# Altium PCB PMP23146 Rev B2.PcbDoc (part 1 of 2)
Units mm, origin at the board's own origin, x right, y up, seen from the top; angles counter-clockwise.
Board outline 35 x 30 mm, 4 copper layers (Top Layer, Int1 (GND), Int2 (PWR), Bottom Layer), stack 0.912 mm thick; 83 components, 52 nets, 312 pads, 74 vias.
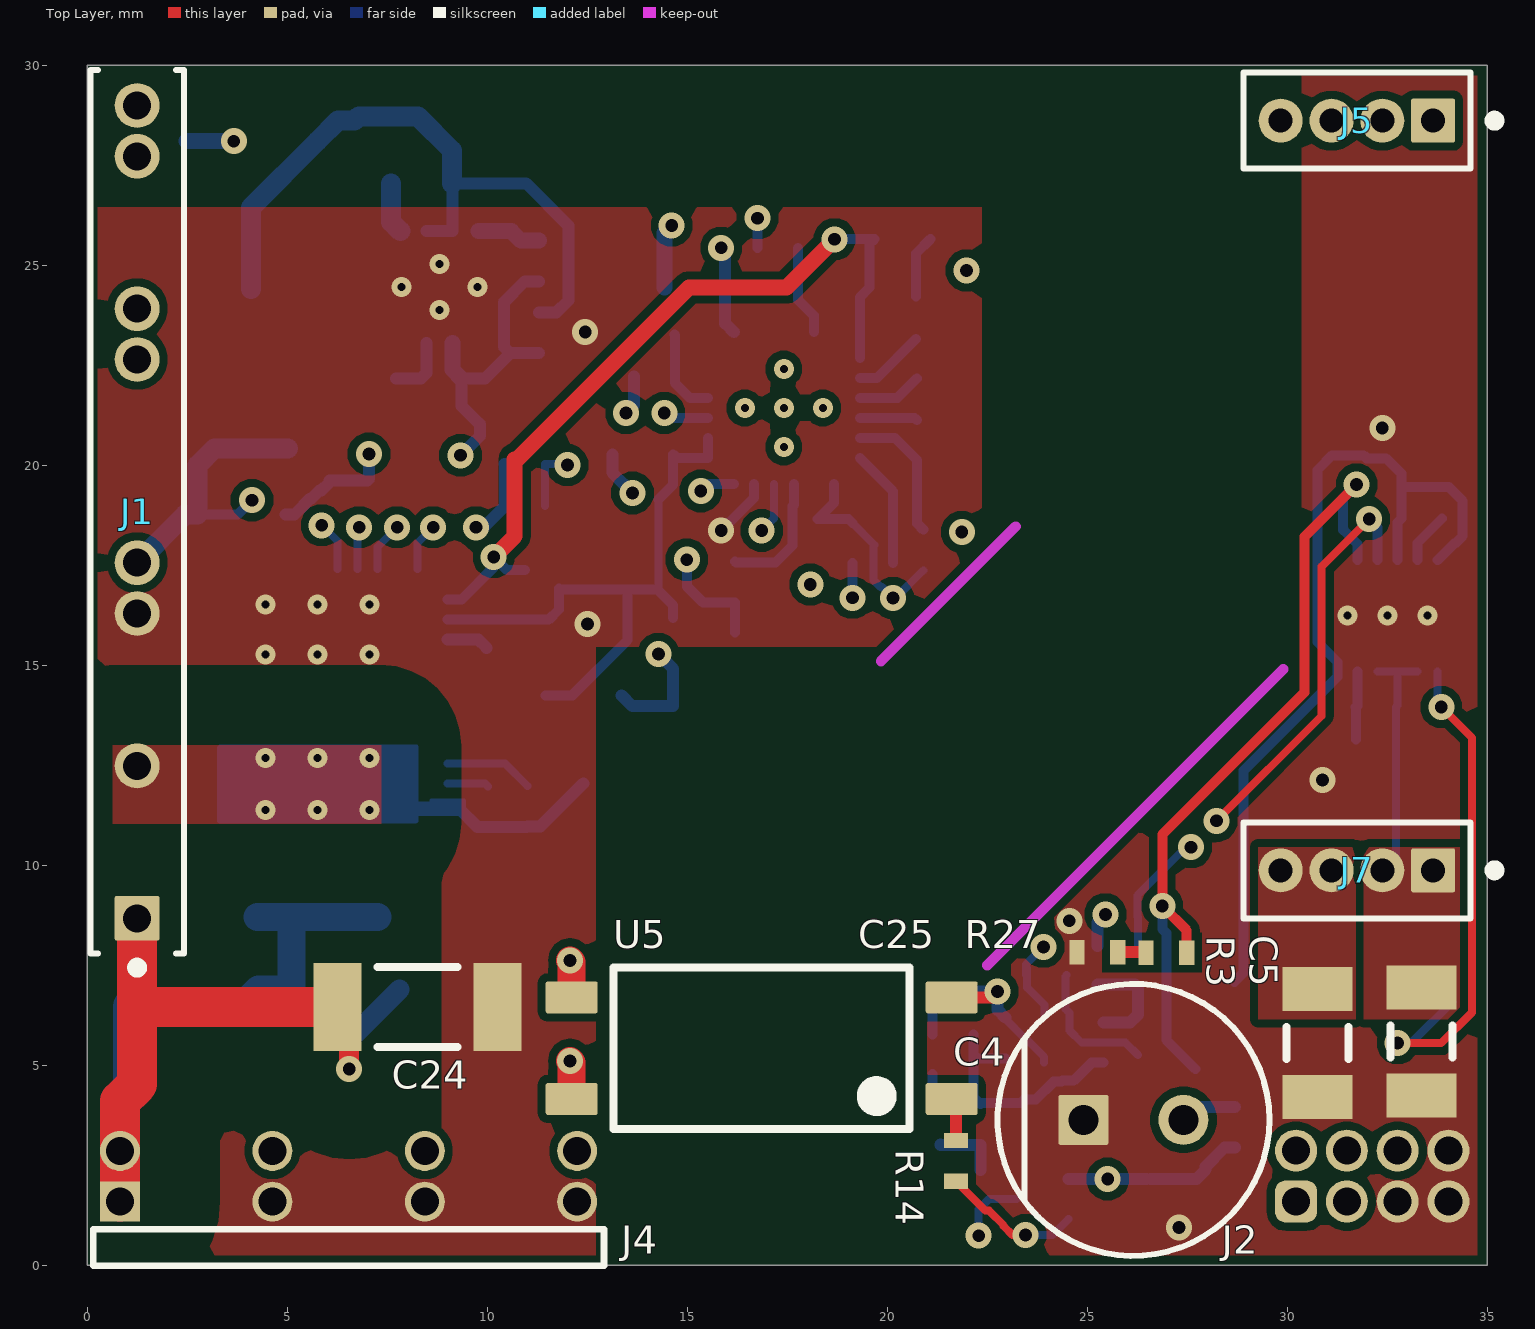
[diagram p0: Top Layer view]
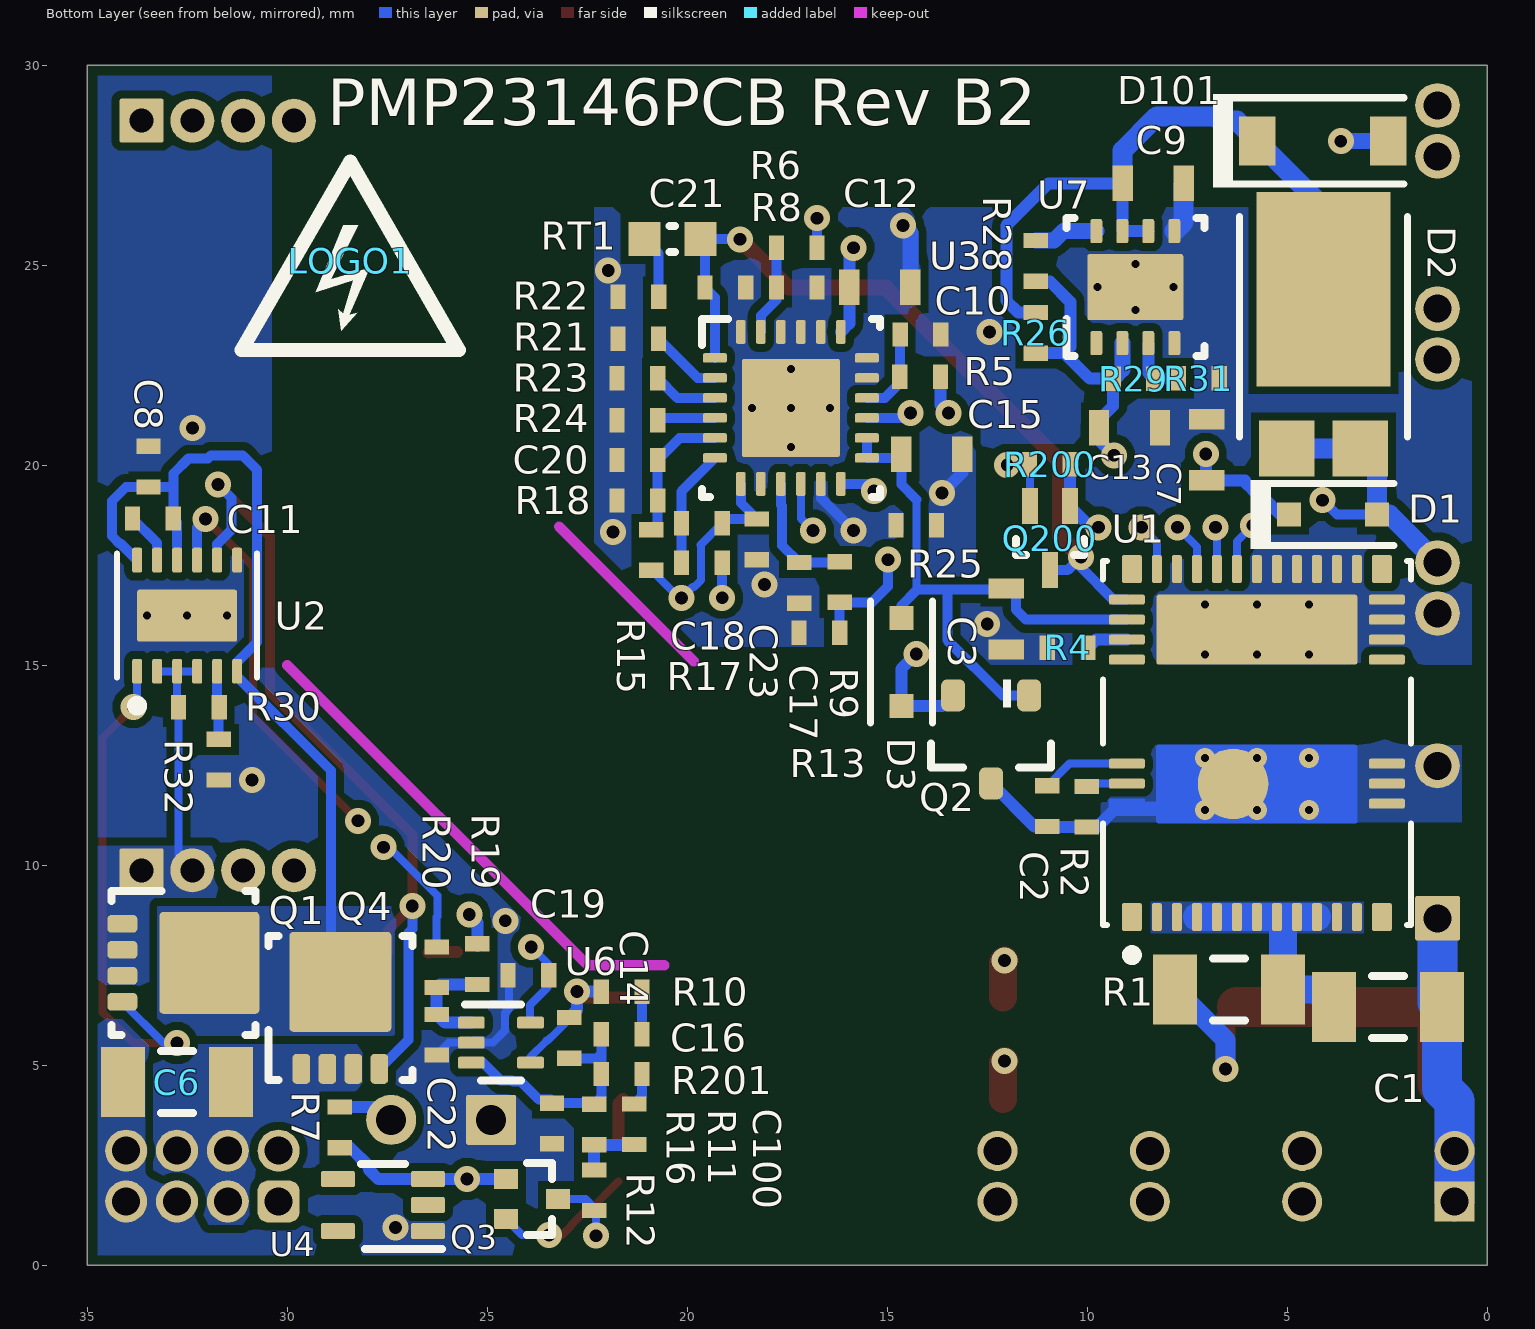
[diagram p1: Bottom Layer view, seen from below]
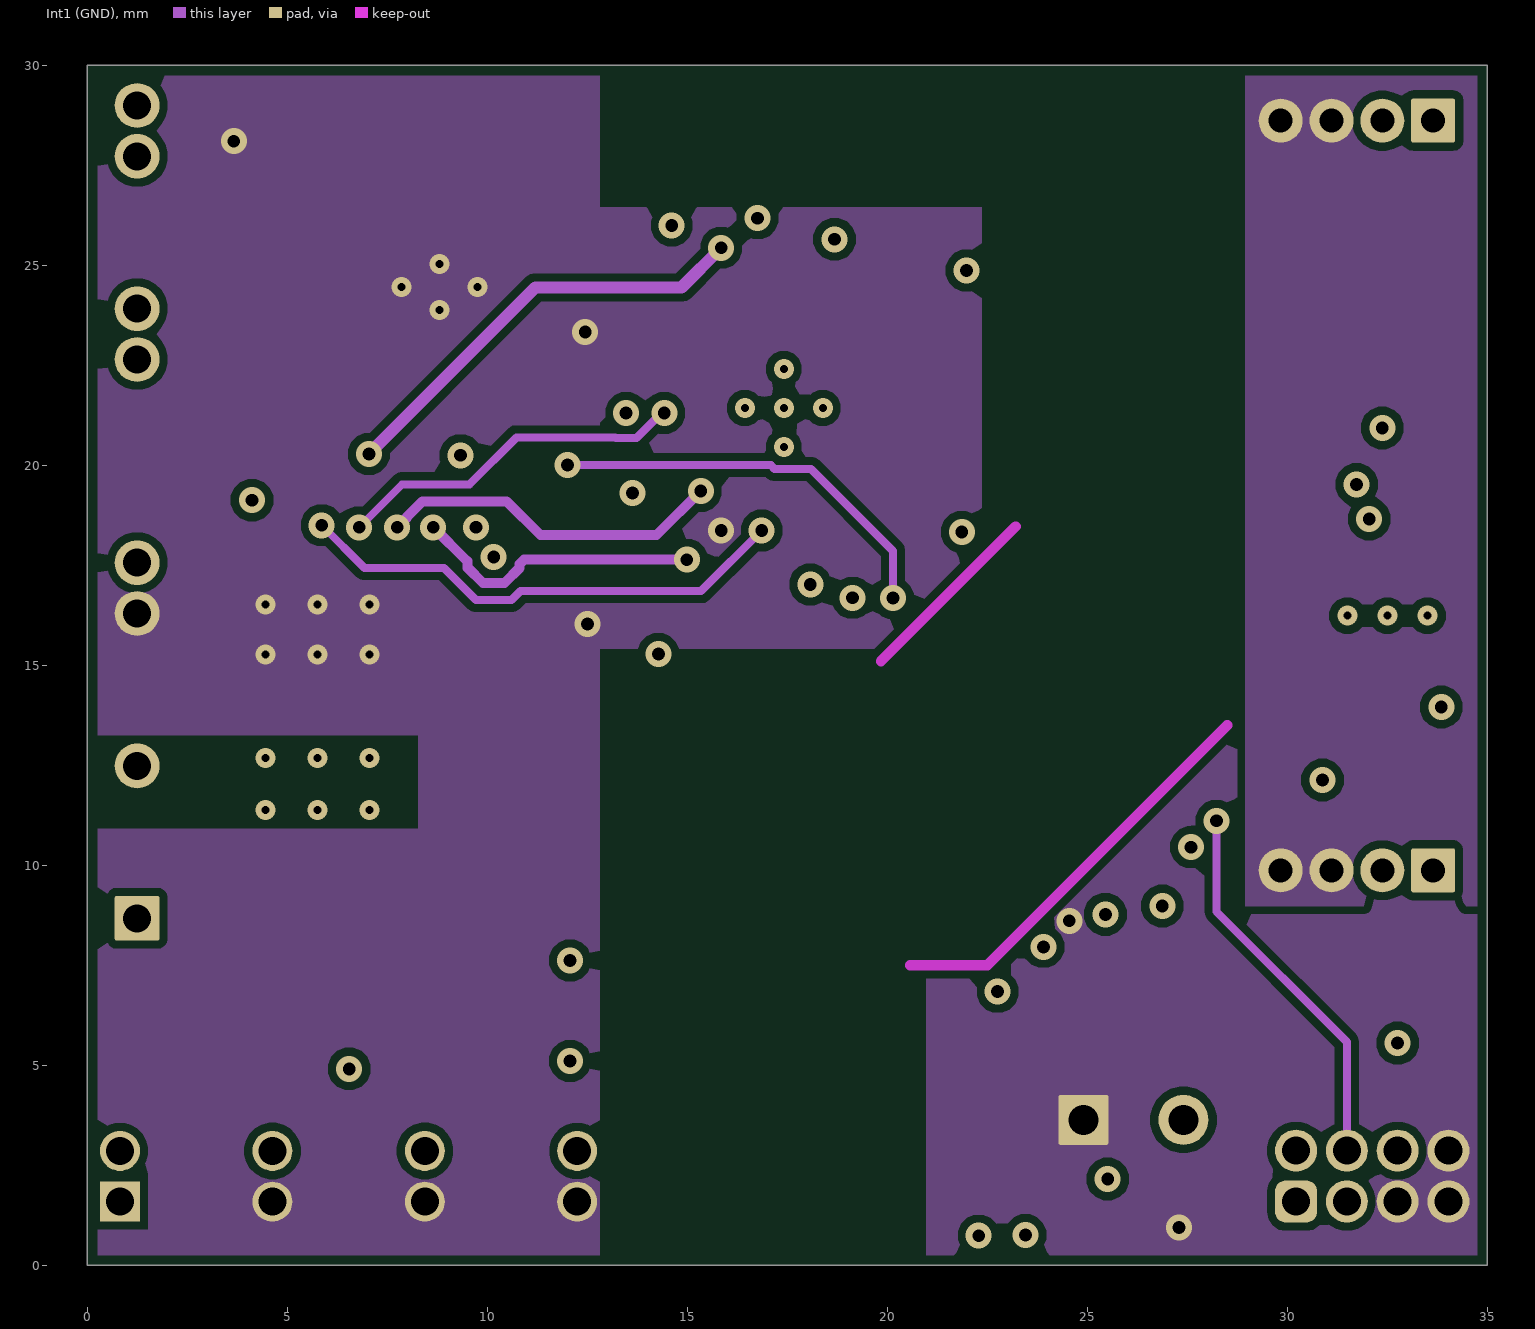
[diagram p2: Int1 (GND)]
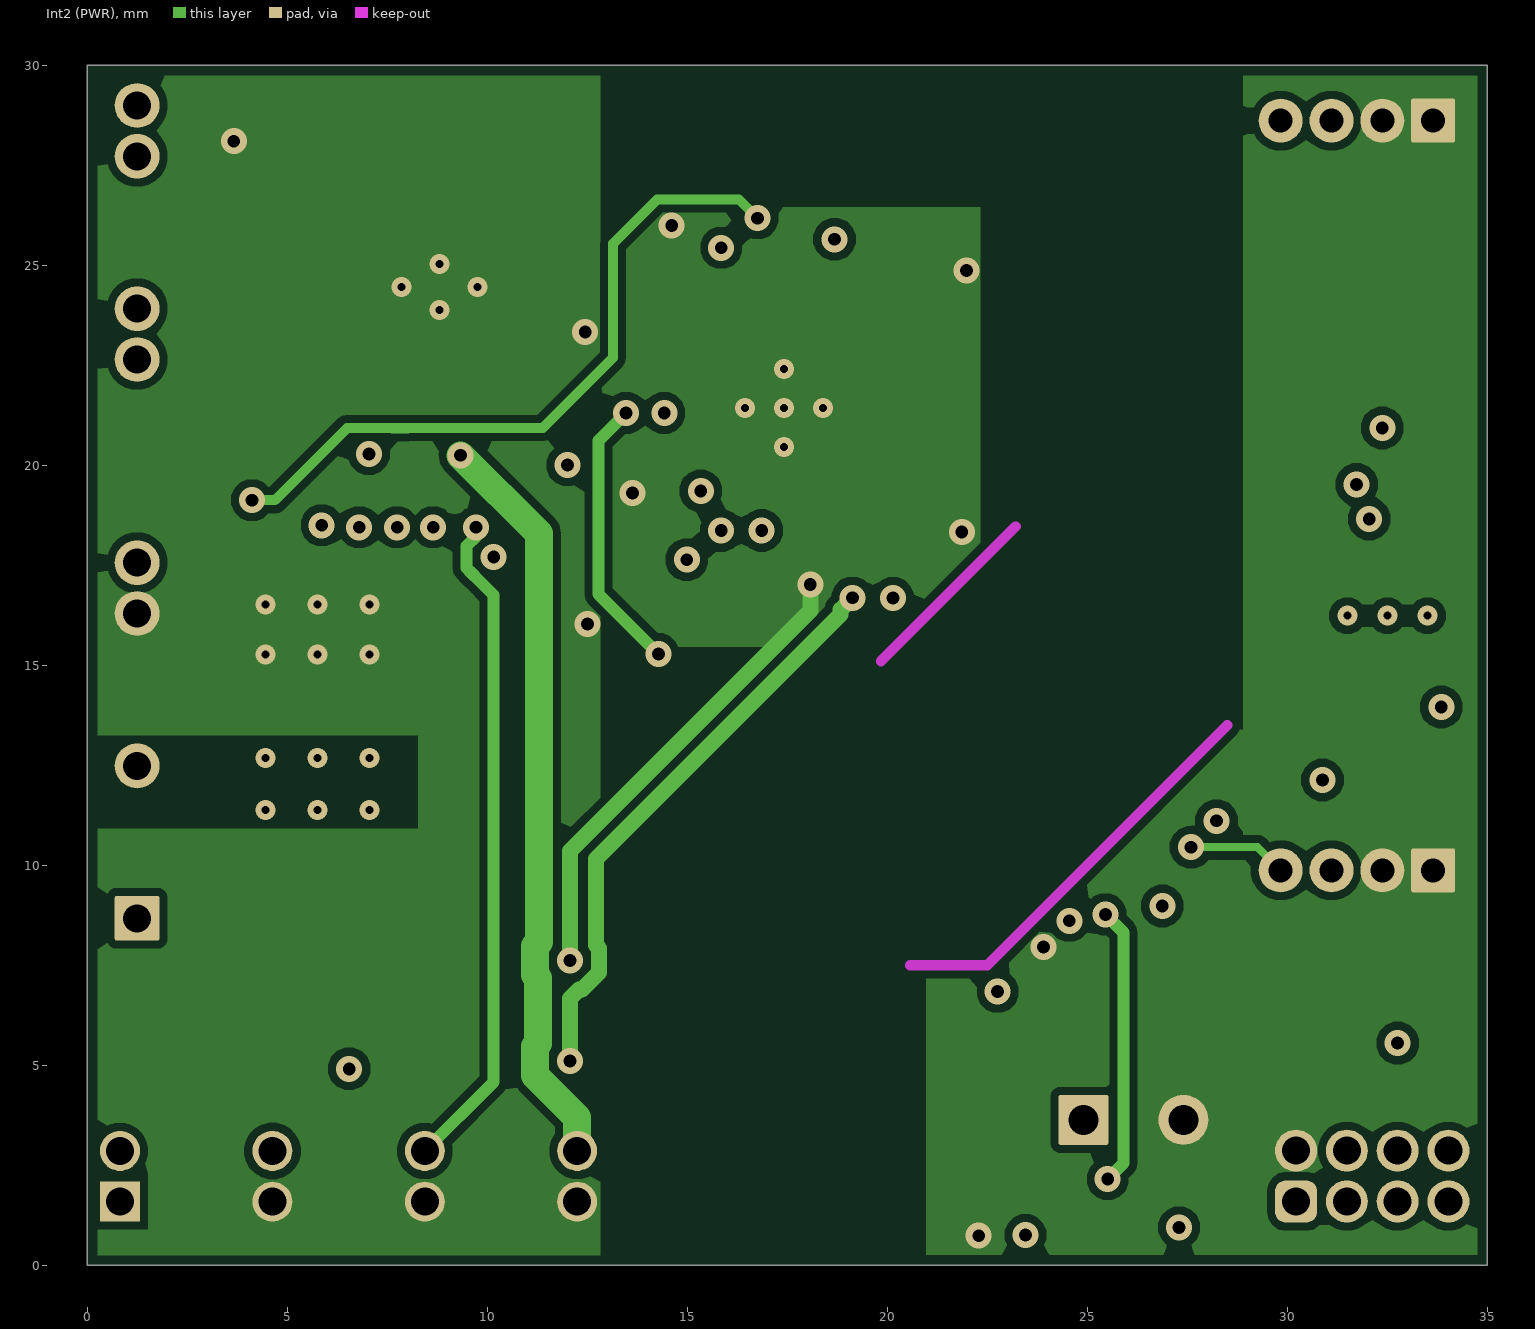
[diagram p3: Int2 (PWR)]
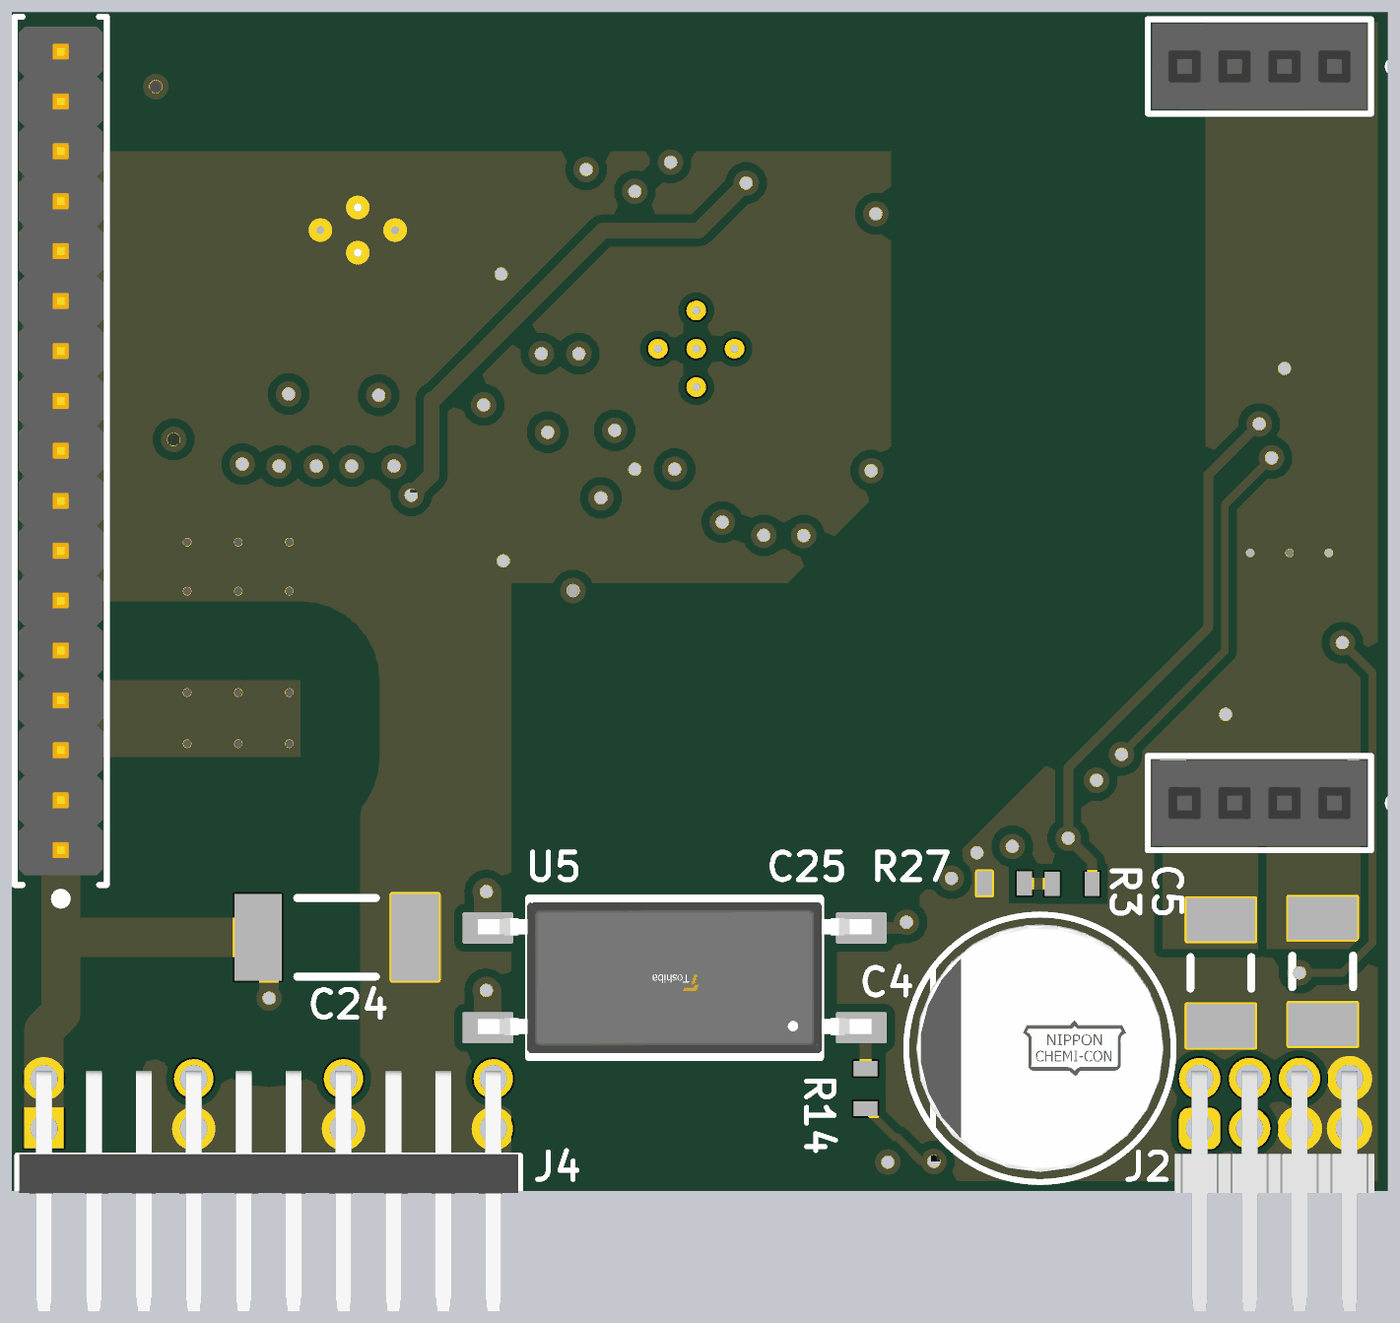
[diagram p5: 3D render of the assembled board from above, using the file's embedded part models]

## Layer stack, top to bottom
Top Solder: solder mask 0.0254, SM-001, Dk 4
Top Layer: signal copper 0.035
Dielectric 1: prepreg 0.1295, PP-017, Dk 4.3
Dielectric 2: prepreg 0.1295, PP-017, Dk 4.3
Int1 (GND): signal copper 0.035
Dielectric 3: core 0.254, Core-028, Dk 4.3
Int2 (PWR): signal copper 0.035
Dielectric 4: prepreg 0.1295, PP-017, Dk 4.3
Dielectric 5: prepreg 0.1295, PP-017, Dk 4.3
Bottom Layer: signal copper 0.035
Bottom Solder: solder mask 0.0254, SM-001, Dk 4

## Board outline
0,0 35,0 35,30 0,30

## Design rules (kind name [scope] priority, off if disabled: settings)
AcuteAngle [All] p1: minimum=5.00000000000000E+0000 checktracksonly=FALSE
AssemblyTestPointUsage [All] p1: valid=2
BoardOutlineClearance BoardOutlineClearance_Pri [InNet('P')] p1: gap=0.4 ignorepadtopadclearanceinfootprint=FALSE
BoardOutlineClearance BoardOutlineClearance_MountingHoles [OnCopper and InComponentClass('Mounting Holes')] p2: gap=0.635 ignorepadtopadclearanceinfootprint=FALSE
BoardOutlineClearance BoardOutlineClearance_Poly [OnCopper and InPoly] p3: gap=0.25 ignorepadtopadclearanceinfootprint=FALSE
BoardOutlineClearance [OnCopper and Not InComponentClass('Logo') and not InComponentClass('FiducialMark') and not InRegion(1000,500,4000,800)] p4: gap=0.25 ignorepadtopadclearanceinfootprint=FALSE
Clearance "Pri To Sec Inner Layers" [InNet('S') vs InNet('A')  Or InNet('B')] p1: gap=0.5 ignorepadtopadclearanceinfootprint=TRUE
Clearance "400V Clearance" [(InNetClass('400V') AND (OnTopLayer Or OnBottomLayer)) vs (InNetClass('Primary LV'))] p2: gap=2 ignorepadtopadclearanceinfootprint=TRUE
Clearance "Float Bias Clearance" [(InNetClass('BIAS_FLOAT') AND (OnTopLayer Or OnBottomLayer)) vs (InNetClass('Primary LV'))] p3: gap=2.2 ignorepadtopadclearanceinfootprint=TRUE
Clearance Clearance_Keepouts [((IsTrack Or IsArc) And Not InPoly) And IsFree and IsKeepOut vs ((IsTrack Or IsArc) And Not InPoly) And IsFree and IsKeepOut] p4: gap=0 ignorepadtopadclearanceinfootprint=TRUE
Clearance Clearance_Poly [InPolygon] p5: gap=0.203 ignorepadtopadclearanceinfootprint=TRUE except(0: Arc-Hole Track-Hole SMDPad-Hole THPad-Hole Via-Hole Fill-Hole Poly-Hole Region-Hole Text-Hole)
Clearance [All] p6: gap=0.2 ignorepadtopadclearanceinfootprint=TRUE except(0: Arc-Hole Track-Hole SMDPad-Hole THPad-Hole Via-Hole Fill-Hole Poly-Hole Region-Hole Text-Hole)
ComponentClearance ComponentClearance_MountingHoles_FiducialMarks [InComponentClass('Mounting Holes') vs InComponentClass('FiducialMark')] p1: gap=1.27 collisioncheckmode=3 verticalgap=0.254 showdistances=FALSE
ComponentClearance ComponentClearance_Shunt [InComponentClass('Header') vs InComponentClass('Shunt')] p2: gap=0 collisioncheckmode=3 verticalgap=0 showdistances=FALSE
ComponentClearance ComponentClearance_Logo [InComponentClass('Logo')] p3: gap=1.27 collisioncheckmode=3 verticalgap=0.254 showdistances=FALSE
ComponentClearance ComponentClearance_ScrewToNut [(HasFootprint('NY PMS 440 0025 PH')) vs (HasFootprint('Keystone_1902C'))] p4: gap=0.127 collisioncheckmode=3 verticalgap=0.254 showdistances=FALSE
ComponentClearance ComponentClearance_MountingHoles [InComponentClass('Mounting Holes')] p5: gap=6.35 collisioncheckmode=3 verticalgap=2540 showdistances=FALSE
ComponentClearance ComponentClearance_SmallPassives [HasFootprint('0201*') or HasFootprint('0402*') or HasFootprint('0508') or HasFootprint('0603*') or HasFootprint('0612') or HasFootprint('0805*') or HasFootprint('0815*') or HasFootprint('0830*') or HasFootprint('1206*') or HasFootprint('1210*') or HasFootprint('1808*') or HasFootprint('1812*') or HasFootprint('1825*') or HasFootprint('2010*') or HasFootprint('2220*') or HasFootprint('2225*') or HasFootprint('2512*') or HasFootprint('2728*') or HasFootprint('3518*') vs HasFootprint('0201*') or HasFootprint('0402*') or HasFootprint('0508') or HasFootprint('0603*') or HasFootprint('0612') or HasFootprint('0805*') or HasFootprint('0815*') or HasFootprint('0830*') or HasFootprint('1206*') or HasFootprint('1210*') or HasFootprint('1808*') or HasFootprint('1812*') or HasFootprint('1825*') or HasFootprint('2010*') or HasFootprint('2220*') or HasFootprint('2225*') or HasFootprint('2512*') or HasFootprint('2728*') or HasFootprint('3518*')] p6: gap=0.38 collisioncheckmode=3 verticalgap=0.254 showdistances=FALSE
ComponentClearance ComponentClearance_THtoSMT [IsThruComponent vs IsSMTComponent] p7: gap=0.381 collisioncheckmode=3 verticalgap=0.762 showdistances=FALSE
ComponentClearance ComponentClearance_THtoTH [IsThruComponent vs IsThruComponent] p8: gap=0.381 collisioncheckmode=3 verticalgap=0.762 showdistances=FALSE
ComponentClearance [All] p9: gap=0.381 collisioncheckmode=3 verticalgap=0.254 showdistances=FALSE
DiffPairsRouting [All] p1: maxlimit=2.54 minlimit=0.254 mostfreqgap=0.254 toplayer_minwidth=0.381 toplayer_maxwidth=0.381 toplayer_prefwidth=0.381 midlayer1_minwidth=0.381 midlayer1_maxwidth=0.381 midlayer1_prefwidth=0.381 midlayer2_minwidth=0.381 midlayer2_maxwidth=0.381 midlayer2_prefwidth=0.381 bottomlayer_minwidth=0.381 bottomlayer_maxwidth=0.381 bottomlayer_prefwidth=0.381 maxuncoupledlength=25.4
FabricationTestPointUsage TestPointUsage [All] p1: valid=2 allowmultiple=FALSE
FabricationTestpoint Testpoint [All] p1: side=3 testpointundercomponent=TRUE minsize=1.016 maxsize=2.54 preferedsize=1.524 minholesize=0 maxholesize=1.016 preferedholesize=0.813 testpointgrid=0.025 allowsidetop=TRUE allowsidebottom=TRUE usegrid=TRUE gridtolerance=0
FanoutControl Fanout_LCC [IsLCC] p1: bgadir=Out bgaviamode=Centered fanoutstyle=Auto fanoutdirection=Alternating viagrid=0.025 // Fanout_LCC (Default Rule)
FanoutControl Fanout_BGA [IsBGA] p2: bgadir=Out bgaviamode=Centered fanoutstyle=Auto fanoutdirection=Alternating viagrid=0.025 // Fanout_BGA (Default Rule)
FanoutControl Fanout_Default [All] p4: bgadir=Out bgaviamode=Centered fanoutstyle=Auto fanoutdirection=Alternating viagrid=0.025 // Fanout_Default (Default Rule)
FanoutControl Fanout_Small [(CompPinCount < 5)] p5: bgadir=Out bgaviamode=Centered fanoutstyle=Auto fanoutdirection=OutThenIn viagrid=0.025 // Fanout_Small (Default Rule)
HoleSize [All] p1: absolutevalues=TRUE maxlimit=6.375 minlimit=0.2 maxpercent=80.000 minpercent=20.000
MinimumAnnularRing MinimumAnnularRing_ThermalPadVias [IsVia and InAnyComponent] p1: minimumring=0.15
MinimumAnnularRing [All] p2: minimumring=0.15
MinimumSolderMaskSliver MinimumSolderMaskSliver_Logo [InComponentClass('Logo') vs InComponentClass('Logo')] p1 off: minsoldermaskwidth=0.018
MinimumSolderMaskSliver [All] p2 off: minsoldermaskwidth=0.025
PlaneConnect [All] p1: planeconnectstyle=Direct reliefexpansion=0.254 reliefentries=4 reliefconductorwidth=0.254 reliefairgap=0.254
PolygonConnect [All] p1: connectstyle=Direct reliefconductorwidth=0.381 reliefentries=4 polygonreliefangle="90 Angle" airgapwidth=0.254
RoutingVias ThermalPadVias [IsVia and InAnyComponent] p1: holewidth=0.2 width=0.5 viastyle="Through Hole" minholewidth=0.2 minwidth=0.5 maxholewidth=0.33 maxwidth=0.6
RoutingVias [All] p2: holewidth=0.406 width=0.864 viastyle="Through Hole" minholewidth=0.2 minwidth=0.65 maxholewidth=1.016 maxwidth=1.651
SilkToBoardRegionClearance [Not ((IsComment or IsDesignator) And (Hide <> 'False')) and not InRegion(1000,500,4000,800)] p1:
SilkToSilkClearance SilkToSilkClearance_Pb-FreeLogo [(HasFootprint('Pb-Free_Overlay_Medium') OR HasFootprint('Pb-Free_Overlay_Small')) vs (HasFootprint('Pb-Free_Overlay_Medium') OR HasFootprint('Pb-Free_Overlay_Small'))] p1: silktosilkclearance=0
SilkToSilkClearance [All] p2: silktosilkclearance=0.025
SilkToSolderMaskClearance SilkToComponentPadClearance [IsPad and InAnycomponent] p1: minsilkscreentomaskgap=0 clearancetoexposedcopper=TRUE
SilkToSolderMaskClearance "Silk to Solder Mask Opening" [All] p2: minsilkscreentomaskgap=0 clearancetoexposedcopper=FALSE
SolderMaskExpansion [All] p1: expansion=0.05 istentingtop=FALSE
Width [All] p1: maxlimit=4 minlimit=0.152 preferedwidth=0.254 checkconnectedcopper=TRUE
15 further rules are at their usual default settings.

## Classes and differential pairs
net class "Primary LV": PWRGND
net class 400V: NetC1_2 VDCIN VSWN
component class Header: J2

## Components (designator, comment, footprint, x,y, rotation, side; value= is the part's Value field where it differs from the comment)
C1 "C3216X7T2E224K160AA" 1206_190L 2.487,6.46 r0 bottom value=0.22uF
C2 "GRM155R71H223KA12D" 0402S 10.999,11.479 r270 bottom value=0.022uF
C3 "C1608X7R1E105K080AB" 0603S 12.026,16.158 r90 bottom value=1uF
C4 "APSG160ELL271MF08J" FP-APSG160ELL271MF08J_RADIAL-MFG 26.153,3.636 r0 top value=270µF
C5 "C3216X5R1V226M160AC" 1206_180L 33.348,5.592 r90 top value=22uF
C6 "C3216X5R1V226M160AC" 1206_180L 32.758,4.581 r0 bottom value=22uF
C7 "GRM188R6YA106MA73D" 0603S 7.011,20.389 r90 bottom value=10uF
C8 "GRM155R71E104KE14D" 0402S 33.469,19.968 r90 bottom value=0.1uF
C9 "GRM188R6YA106MA73D" 0603S 8.353,27.051 r180 bottom value=10uF
C10 "GRM1555C1H220JA01D" 0402S 14.17,23.272 r0 bottom value=22pF
C11 "GRM155R71E104KE14D" 0402S 33.362,18.671 r0 bottom value=0.1uF
C12 "GRM188R6YA106MA73D" 0603S 15.186,24.449 r180 bottom value=10uF
C13 "GRM188R6YA106MA73D" 0603S 8.945,20.934 r180 bottom value=10uF
C14 "GRM1555C1H101JA01D" 0402S 22.951,5.685 r270 bottom value=100pF
C15 "C1608X7R1E105K080AB" 0603S 13.886,20.274 r0 bottom value=1uF
C16 "GRM155R71E473KA88D" 0402S 21.642,5.775 r180 bottom value=0.047uF
C17 "GRM1555C1H330JA01D" 0402S 17.202,17.061 r270 bottom value=33pF
C18 "GRM155R71H331KA01D" 0402S 19.636,18.555 r180 bottom value=330pF
C19 "GRM155R71E104KE14D" 0402S 23.973,7.255 r180 bottom value=0.1uF
C20 "GRM155R71H331KA01D" 0402S 21.249,20.134 r180 bottom value=330pF
C21 "GRM1555C1H101JA01D" 0402S 19.049,24.444 r180 bottom value=100pF
C22 "C1005X5R1A474K050BB" 0402S 26.269,5.764 r90 bottom value=0.47uF
C23 "GRM155R71C224KA12D" 0402S 18.26,18.149 r270 bottom value=0.22uF
C24 "C1808W104KBRACTU" 1808_215_L 8.261,6.46 r0 top value=0.1uF
C25 "GCM155R71E103KA37D" 0402S 25.251,7.828 r0 top value=0.01uF
C100 "GCM155R71E103KA37D" 0402S 21.327,3.527 r270 bottom value=0.01uF
D1 "BAS20HT1G" SOD-323 3.857,18.769 r180 bottom value=200V
D2 "PDS3200-13" POWERDI5 4.095,22.414 r90 bottom value=200V
D3 "DF2B18FU" SOD-323-Bi 14.648,15.081 r90 bottom value=16.2V
D101 "MMSZ4707-E3-08" SOD-123 4.117,28.11 r180 bottom value=20V
J1 "LPPB171NFFN-RC" FP-GRPB171VWVN-RC_HDR17-MFG 1.245,18.836 r90 top
J2 "GRPB042MWCN-RC" Sullins_GRPB042MWCN 32.123,2.231 r90 top
J4 "GRPB102MWCN-RC" Sullins_GRPB102MWCN-modified 6.532,2.225 r0 top
J5 "LPPB041NFFN-RC" FP-LPPB041NFFN-RC_HDR04-MFG 31.74,28.617 r180 top
J7 "LPPB041NFFN-RC" FP-LPPB041NFFN-RC_HDR04-MFG 31.74,9.875 r180 top
LOGO1 "DANGER HIGH VOLTAGE" IEC_HighVoltage_Small 28.428,25.115 r180 bottom
Q1 "CSD17575Q3" DQG0008A_NV 32.599,7.562 r180 bottom value=30V
Q2 "BSS126" SOT-23L 12.405,13.15 r270 bottom value=600V
Q3 "MMBT2222ATT1G" SOT-416 23.884,1.656 r180 bottom value="40 V"
Q4 "CSD17575Q3" DQG0008A_NV 28.675,6.436 r90 bottom value=30V
Q200 "DMP22D6UT-7" SOT-523 10.939,18.177 r270 bottom value=-20V
R1 "CRCW12061M00JNEA" 1206L 6.457,6.899 r0 bottom value=1.0Meg
R2 "CRCW0402121KFKED" 0402S 10.015,11.465 r90 bottom value=121k
R3 "CSR1206FK10L0" 1206L 30.758,5.556 r270 top value=0.01
R4 "CRCW0402121KFKED" 0402S 10.491,15.438 r0 bottom value=121k
R5 "CRCW0402511RFKED" 0402S 14.18,22.218 r180 bottom value=511
R6 "CRCW040251K1FKED" 0402S 17.264,25.438 r180 bottom value=51.1k
R7 "CRCW040210K0FKED" 0402S 28.688,3.449 r90 bottom value=10.0k
R8 "CRCW04029K31FKED" 0402S 17.264,24.444 r0 bottom value=9.31k
R9 "CRCW0402511RFKED" 0402S 16.19,17.083 r90 bottom value=511
R10 "CRCW04027K50FKED" 0402S 21.642,6.843 r180 bottom value=7.50k
R11 "MCR01MRTF1002" 0402S 22.328,3.521 r270 bottom value=10.0k
R12 "CRCW04020000Z0ED" 0402S 22.328,1.877 r90 bottom value=0
R13 "CRCW0402150RFKED" 0402S 16.698,15.816 r180 bottom value=150
R14 "CRCW04024K99FKED" 0402S 21.718,2.609 r270 top value=4.99k
R15 "CRCW0402200KFKED" 0402S 20.899,17.884 r270 bottom value=200k
R16 "ERA-2AEB1051X" 0402S 23.384,3.545 r90 bottom value=1.05k
R17 "CRCW040220K0FKED" 0402S 19.636,17.561 r180 bottom value=20.0k
R18 "CRCW040241K2FKED" 0402S 21.249,19.119 r180 bottom value=41.2k
R19 "RG1005P-104-B-T5" 0402S 25.248,7.532 r270 bottom value=100k
R20 "ERA-2AEB3092X" 0402S 26.269,7.45 r270 bottom value=30.9k
R21 "CRCW0402187KFKED" 0402S 21.227,23.162 r180 bottom value=187k
R22 "CRCW04020000Z0ED" 0402S 21.224,24.216 r180 bottom value=0
R23 "CRCW040271K5FKED" 0402S 21.249,22.176 r180 bottom value=71.5k
R24 "CRCW04020000Z0ED" 0402S 21.249,21.129 r180 bottom value=0
R25 "CRCW04020000Z0ED" 0402S 14.276,18.499 r180 bottom value=0
R26 "CRCW04020000Z0ED" 0402S 11.289,23.311 r270 bottom value=0
R27 "CRCW0402100RFKED" 0402S 26.975,7.817 r0 top value=100
R28 "CRCW0402100KFKED" 0402S 11.289,25.109 r270 bottom value=100k
R29 "CRCW040251K1FKED" 0402S 8.845,22.168 r0 bottom value=51.1k
R30 "CRCW0402121KFKED" 0402S 32.212,13.956 r0 bottom value=121k
R31 "CRCW04023K74FKED" 0402S 7.211,22.176 r0 bottom value=3.74k
R32 "CRCW040210K0FKED" 0402S 31.715,12.642 r90 bottom value=10.0k
R200 "CRCW040210K0FKED" 0402S 10.939,20.029 r0 bottom value=10.0k
R201 "CRCW04021K50FKED" 0402S 21.642,4.784 r180 bottom value=1.50k
RT1 "CRCW060346K4FKEA" 0603L 20.375,25.654 r0 bottom value=46.4k
U1 "LMG2610" RRG0040A-C01-MFG 5.761,13.057 r90 bottom
U2 "LM74800" DRR0012E-MFG 32.504,16.239 r90 bottom
U3 "UCC28782ARTW" RTW0024B 17.411,21.434 r180 bottom
U4 "LM4040A50IDCKR" DCK0005A_N 27.608,1.506 r0 bottom
U5 "TLP383(GR-TPL,E" FP-TLP383(GR-TPL,E_SO6-4-MFG 16.86,5.429 r180 top
U6 "OPA170AIDRLT" DRL0005A 24.66,5.567 r180 bottom
U7 "TPS7A1901DRBR" DRB0008B 8.8,24.454 r90 bottom

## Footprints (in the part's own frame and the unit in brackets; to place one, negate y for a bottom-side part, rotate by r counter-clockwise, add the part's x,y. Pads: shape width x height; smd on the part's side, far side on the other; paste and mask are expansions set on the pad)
0402S [mil] "Based on C0402S footprint from PADS legacy"
  rect 15x24 smd: 1(-20,0) 2(20,0)
  body extent -22,-12 22,12, height 24
0603L [mm] "0603 from SM-752 data"
  rect 0.8x0.85 smd: 1(-0.7,0) 2(0.7,0)
  silkscreen extent -0.07,-0.33 0.07,0.33, body extent -0.87,-0.47 0.87,0.47, height 1
0603S [mil]
  rect 20x35 smd: 1(-30,0) 2(30,0)
  body extent -34,-19 34,19, height 39
1206_180L [mm] "1206_180"
  rect 1.1x1.75 smd: 1(-1.35,0) 2(1.35,0)
  silkscreen extent -0.4,-0.77 0.4,0.77, body extent -1.75,-0.95 1.75,0.95, height 1.8
1206_190L [mm] "1206_190"
  rect 1.1x1.75 smd: 1(-1.35,0) 2(1.35,0)
  silkscreen extent -0.4,-0.77 0.4,0.77, body extent -1.75,-0.95 1.75,0.95, height 1.9
1206L [mm] "1206 from SM-752 data"
  rect 1.1x1.75 smd: 1(-1.35,0) 2(1.35,0)
  silkscreen extent -0.4,-0.77 0.4,0.77, body extent -1.7,-0.9 1.7,0.9, height 1.35
1808_215_L [mm] "Chip Capacitor, Body 4.6x2.0mm, IPC High Density"
  rect 1.2x2.2 smd: 1(-2,0) 2(2,0)
  silkscreen extent -1,-1 1,1, body extent -2.47,-1.2 2.47,1.2, height 2.15
DCK0005A_N [mm] "SOT353, 5-Leads, Body 2x1.3mm, Pitch 0.65mm, Lead Span 2.1mm, IPC Medium Density"
  rrect25% 0.85x0.4 smd: 1(-1.125,0.65) 2(-1.125,0) 3(-1.125,-0.65) 4(1.125,-0.65) 5(1.125,0.65)
  silkscreen extent -1.48,-1.02 0.55,1.1, body extent -1.14,-1 1.14,1, height 0.95
DQG0008A_NV [mm] "SMD, 8-Leads, Body 3.3x3.3mm, Pitch 0.65mm"
  rrect45% 0.75x0.44 smd paste-0.05 mask-0.05: 1(-1.525,0.975) 2(-1.525,0.325) 3(-1.525,-0.325) 4(-1.525,-0.975) 5(1.525,-0.975) 6(1.525,-0.325) 7(1.525,0.325) 8(1.525,0.975)
  rrect15% 0.676x1.125 on Bottom Paste: 9(-0.212,-0.663) 9(-0.212,0.662) 9(0.664,-0.663) 9(0.664,0.662)
  rrect6% 1.775x2.45 on Bottom Solder: 9(0.327,0)
  rrect8% 2.5x2.55 smd paste-1.5 mask-1.5: 9(0.65,0)
  rrect29% 0.5x0.34 on Bottom Solder: 9(1.175,-0.975) 9(1.175,-0.325) 9(1.175,0.325) 9(1.175,0.975)
  silkscreen extent -1.8,-1.8 1.8,1.8, body extent -1.65,-1.65 1.65,1.65, height 1.1
DRB0008B [mm] "SON, 8-Leads, Body 3x3mm, Pitch 0.65mm, Thermal Pad 2.4x1.65mm, TI Recommended"
  rrect33% 0.6x0.3 smd: 1(-1.4,0.975) 2(-1.4,0.325) 3(-1.4,-0.325) 4(-1.4,-0.975) 5(1.4,-0.975) 6(1.4,-0.325) 7(1.4,0.325) 8(1.4,0.975)
  rrect9% 1.47x1.06 on Bottom Paste: 9(0,-0.63) 9(0,0.63)
  rrect6% 1.65x2.4 smd paste-1.2: 9(0,0)
  silkscreen extent -1.73,-1.73 1.73,1.73, body extent -1.5,-1.5 1.5,1.5, height 0.96
DRL0005A [mm] "SOTFL, 5-Flat Leads, Body 1.2x1.6x0.6mm, Pitch 0.5mm, TI recommended"
  rrect33% 0.67x0.3 smd: 1(-0.74,0.5) 2(-0.74,0) 3(-0.74,-0.5) 4(0.74,-0.5) 5(0.74,0.5)
  silkscreen extent -0.9,-0.95 0.5,0.95, body extent -0.85,-0.85 0.85,0.85, height 0.62
DRR0012E-MFG [mm]
  rrect40% 0.62x0.25 smd paste+0 mask+0: 1(-1.39,1.25) 2(-1.39,0.75) 3(-1.39,0.25) 4(-1.39,-0.25) 5(-1.39,-0.75) 6(-1.39,-1.25) 7(1.39,-1.25) 8(1.39,-0.75) 9(1.39,-0.25) 10(1.39,0.25) 11(1.39,0.75) 12(1.39,1.25)
  rrect8% 1.3x2.5 smd paste-1000 mask+0: 13(0,0)
  silkscreen extent -2.37,-1.75 1.55,1.75, body extent -1.5,-1.5 1.5,1.5, height 0.8
FP-APSG160ELL271MF08J_RADIAL-MFG [mm]
  rrect8% 1.25x1.25 hole 0.75 paste-1000 mask+0: 1(-1.25,0)
  round 1.25 hole 0.75 paste-1000 mask+0: 2(1.25,0)
  silkscreen extent -3.4,-3.4 3.4,3.4, body extent -3.5,-3.5 3.5,3.5, height 0.25
FP-GRPB171VWVN-RC_HDR17-MFG [mm]
  rrect9% 1.12x1.12 hole 0.7 paste-1000 mask+0: 1(-10.16,0)
  round 1.12 hole 0.7 paste-1000 mask+0: 4(-6.35,0) 7(-2.54,0) 8(-1.27,0) 12(3.81,0) 13(5.08,0) 16(8.89,0) 17(10.16,0)
  silkscreen extent -11.52,-1.17 11.04,1.17, body extent -11.14,-1.27 11.14,1.27, height 0.25
FP-LPPB041NFFN-RC_HDR04-MFG [mm]
  rrect9% 1.1x1.1 hole 0.6 paste-1000 mask+0: 1(-1.905,0)
  round 1.1 hole 0.6 paste-1000 mask+0: 2(-0.635,0) 3(0.635,0) 4(1.905,0)
  silkscreen extent -3.57,-1.2 2.84,1.2, body extent -2.94,-1.3 2.94,1.3, height 0.25
FP-TLP383(GR-TPL,E_SO6-4-MFG [mm]
  rrect13% 1.3x0.8 smd paste+0 mask+0: 1(-4.75,1.27) 3(-4.75,-1.27) 4(4.75,-1.27) 6(4.75,1.27)
  silkscreen extent -3.7,-2.02 3.7,2.02, body extent -5.5,-2.12 5.5,2.12, height 0.25
IEC_HighVoltage_Small [mm]
  silkscreen extent -2.72,-2.24 2.72,2.47
POWERDI5 [mm] "Diodes Inc recommended land pattern, ap02001.pdf rev 60"
  rect 1.4x1.39 smd: 1(-1.991,0.92) 2(-1.991,-0.92)
  rect 4.86x3.36 smd: 3(1.991,0)
  silkscreen extent -1.7,-2.1 3.8,2.1, body extent -2.27,-2.02 4.33,2.03, height 1.17
RRG0040A-C01-MFG [mm]
  rrect20% 0.7x0.5 smd paste+0 mask+0: 1(-4.35,3.125) 13(-4.35,-3.125) 21(4.35,-3.125) 33(4.35,3.125)
  rrect40% 0.7x0.25 smd paste+0 mask+0: 2(-4.35,2.5) 3(-4.35,2) 4(-4.35,1.5) 5(-4.35,1) 6(-4.35,0.5) 7(-4.35,0) 8(-4.35,-0.5) 9(-4.35,-1) 10(-4.35,-1.5) 11(-4.35,-2) 12(-4.35,-2.5) 22(4.35,-2.5) 23(4.35,-2) 24(4.35,-1.5) 25(4.35,-1) 26(4.35,-0.5) 27(4.35,0) 28(4.35,0.5) 29(4.35,1) 30(4.35,1.5) 31(4.35,2) 32(4.35,2.5)
  rrect40% 0.25x0.9 smd paste+0 mask+0: 14(-1.515,-3.25) 15(-1.015,-3.25) 16(-0.515,-3.25) 17(2.085,-3.25) 18(2.585,-3.25) 19(3.085,-3.25) 20(3.585,-3.25) 34(3.585,3.25) 35(3.085,3.25) 36(2.585,3.25) 37(2.085,3.25) 38(-0.515,3.25) 39(-1.015,3.25)
  round 1.764 smd paste-1000 mask-1000: 40-41(-1.02,0.595)
  rrect6% 1.75x5.02 smd paste-1000 mask+0: 42(2.835,0)
  Top Layer region: -1.64,3.65 -1.633,3.675 -1.615,3.693 -1.59,3.7 -1.59,3.7 -1.44,3.7 -1.421,3.696 -1.405,3.685 -1.394,3.669 -1.39,3.65 -1.39,3.65 -1.39,2.85 -1.394,2.831 -1.405,2.815 -1.421,2.804 -1.44,2.8 -1.44,2.8 -1.465,2.8 -1.465,2.51 -0.09,2.51 -0.071,2.506 -0.055,2.495 -0.044,2.479 -0.04,2.46 -0.04,2.46 -0.04,-2.46 -0.09,-2.51 -1.95,-2.51 -1.975,-2.503 -1.993,-2.485 -2,-2.46 -2,-2.46 -2,2.46 -1.993,2.485 -1.975,2.503 -1.95,2.51 -1.95,2.51 -1.565,2.51 -1.565,2.8 -1.59,2.8 -1.609,2.804 -1.625,2.815 -1.636,2.831 -1.64,2.85 -1.64,2.85
  silkscreen extent -5.42,-3.85 4.55,3.85, body extent -4.5,-3.5 4.5,3.5, height 1
RTW0024B [mm] "QFN, 24-Leads, Body 4x4mm, Pitch 0.5mm, Thermal Pad 2.45x2.45mm, TI Recommended"
  rrect42% 0.6x0.24 smd: 1(-1.9,1.25) 2(-1.9,0.75) 3(-1.9,0.25) 4(-1.9,-0.25) 5(-1.9,-0.75) 6(-1.9,-1.25) 13(1.9,-1.25) 14(1.9,-0.75) 15(1.9,-0.25) 16(1.9,0.25) 17(1.9,0.75) 18(1.9,1.25)
  rrect42% 0.24x0.6 smd: 7(-1.25,-1.9) 8(-0.75,-1.9) 9(-0.25,-1.9) 10(0.25,-1.9) 11(0.75,-1.9) 12(1.25,-1.9) 19(1.25,1.9) 20(0.75,1.9) 21(0.25,1.9) 22(-0.25,1.9) 23(-0.75,1.9) 24(-1.25,1.9)
  rrect4% 2.45x2.45 smd paste-1.225: 25(0,0)
  silkscreen extent -2.22,-2.22 2.22,2.22, body extent -2.07,-2.07 2.07,2.07, height 0.81
SOD-123 [mm] "On Semi recommended land pattern"
  rect 0.915x1.22 smd: 1(-1.637,0) 2(1.637,0)
  silkscreen extent -2.74,-1.17 2.03,1.17, body extent -1.93,-0.9 1.93,0.9, height 1.35
SOD-323 [mm] "NXP recommended land pattern"
  rect 0.6x0.6 smd paste-0.05: 1(-1.1,0) 2(1.1,0)
  silkscreen extent -2.06,-0.86 1.53,0.86, body extent -1.3,-0.67 1.3,0.68, height 1.1
SOD-323-Bi [mm] "SOD323, 2-Leads, Body 1.9x1.45mm, No Polarity Mark"
  rect 0.6x0.6 smd paste-0.05: 1(-1.1,0) 2(1.1,0)
  silkscreen extent -1.53,-0.77 1.53,0.77, body extent -1.27,-0.65 1.27,0.65, height 1.02
SOT-23L [mm] "SOT23, 3-Leads, Body 2.9x1.3mm, Pitch 0.95mm, Lead Span 2.5mm, IPC High Density"
  rrect50% 0.8x0.6 smd: 1(-1.1,0.95) 2(-1.1,-0.95) 3(1.1,0)
  silkscreen extent -1.5,-1.5 0.7,1.5, body extent -1.16,-1.45 1.21,1.45, height 1
SOT-416 [mm] "NXP recommended footprint."
  rect 0.6x0.5 smd: 1(-0.65,0.5) 2(-0.65,-0.5) 3(0.65,0)
  silkscreen extent -0.13,-0.9 0.5,0.9, body extent -0.8,-0.9 0.8,0.9, height 0.82
SOT-523 [mm] "From Diodes Inc datasheet component parameters"
  rect 0.9x0.4 smd: 1(-0.8,0.5) 2(-0.8,-0.5) 3(0.8,0)
  silkscreen extent 0.02,-0.85 0.42,0.85, body extent -0.8,-0.8 0.8,0.8, height 0.79
Sullins_GRPB042MWCN [mm] "Header, 1.27mm, 4x2, R/A, TH"
  rrect50% 1.05x1.05 hole 0.7: 1(-0.635,1.905)
  round 1.05 hole 0.7: 2(0.635,1.905) 3(-0.635,0.635) 4(0.635,0.635) 5(-0.635,-0.635) 6(0.635,-0.635) 7(-0.635,-1.905) 8(0.635,-1.905)
  body extent -5.28,-2.54 0.84,2.54, height 3.4
Sullins_GRPB102MWCN-modified [mm] "SULLINS"
  rect 1x1 hole 0.7: 1(-5.715,-0.635)
  round 1 hole 0.7: 2(-5.715,0.635) 7(-1.905,-0.635) 8(-1.905,0.635) 13(1.905,-0.635) 14(1.905,0.635) 19(5.715,-0.635) 20(5.715,0.635)
  silkscreen extent -6.39,-2.23 6.39,-1.32, body extent -6.35,-5.28 6.35,0.84, height 3.41

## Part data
C1: library part CMP-0008726-2, "CAP, CERM, 0.22 uF, 250 V, +/- 10%, X7T, 1206_190", Cap_Case=1206, Manufacturer=TDK, Supplier Part Number 1=445-7756-1-ND, TempCo=X7T, Tolerance_%=10%, Value1=Unknown, Value2=250V, ValueDisplayed=0.22uF
C2: library part CMP-0006684-2, "CAP, CERM, 0.022 uF, 50 V, +/- 10%, X7R, 0402", Cap_Case=0402, Manufacturer=MuRata, Supplier Part Number 1=490-3884-1-ND, TempCo=X7R, Tolerance_%=10%, Value1=Unknown, Value2=50V, ValueDisplayed=0.022uF
C3 C15: library part CMP-0007040-4, "CAP, CERM, 1 µF, 25 V, +/- 10%, X7R, 0603", Cap_Case=0603, Manufacturer=TDK, Supplier Part Number 1=445-5956-1-ND, TempCo=X7R, Tolerance_%=10%, Value1=Unknown, Value2=25V, ValueDisplayed=1uF
C4: library part CMP-0091874-1, "270µF 16V Aluminum - Polymer Capacitors Radial, Can 10mOhm 20000 Hrs @ 105°C", Digikey Part Number=565-4812-ND, Leakage Current=864uA, Manufacturer="Nippon Chemi-Con", Mouser Part Number=661-APSG160E271MF08J, Operating Temperature Range="-55°C to +105°C", Tolerance_%=20%, ValueDisplayed=270uF
C5 C6: library part CMP-0008667-2, "CAP, CERM, 22 uF, 35 V, +/- 20%, X5R, 1206", Cap_Case=1206_180, Manufacturer=TDK, Supplier Part Number 1=445-8045-1-ND, TempCo=X5R, Tolerance_%=20%, Value1="0.002398 ohm", Value2=35V, ValueDisplayed=22uF
C7 C9 C12 C13: library part CMP-0007355-6, "CAP, CERM, 10 uF, 35 V, +/- 20%, X5R, 0603", Cap_Case=0603, Manufacturer=Murata, TempCo=X5R, Tolerance_%=20%, Value1=Unknown, Value2=35V, ValueDisplayed=10uF
C8 C11 C19: library part CMP-0006659-2, "CAP, CERM, 0.1 uF, 25 V, +/- 10%, X7R, 0402", Cap_Case=0402, Manufacturer=MuRata, Supplier Part Number 1=490-10698-1-ND, TempCo=X7R, Tolerance_%=10%, Value1=Unknown, Value2=25V, ValueDisplayed=0.1uF
C10: library part CMP-0006439-2, "CAP, CERM, 22 pF, 50 V, +/- 5%, C0G/NP0, 0402", Cap_Case=0402, Manufacturer=MuRata, Supplier Part Number 1=81-GRM1555C1H220JA1D, TempCo=C0G/NP0, Tolerance_%=5%, Value1=Unknown, Value2=50V, ValueDisplayed=22pF
C14 C21: library part CMP-0006410-2, "CAP, CERM, 100 pF, 50 V, +/- 5%, C0G/NP0, 0402", Cap_Case=0402, Manufacturer=MuRata, Supplier Part Number 1=81-GRM1555C1H101JA1D, TempCo=C0G/NP0, Tolerance_%=5%, Value1=Unknown, Value2=50V, ValueDisplayed=100pF
C16: library part CMP-0006669-2, "CAP, CERM, 0.047 uF, 25 V, +/- 10%, X7R, 0402", Cap_Case=0402, Manufacturer=MuRata, Supplier Part Number 1=490-3254-1-ND, TempCo=X7R, Tolerance_%=10%, Value1=Unknown, Value2=25V, ValueDisplayed=0.047uF
C17: library part CMP-0006454-2, "CAP, CERM, 33 pF, 50 V, +/- 5%, C0G/NP0, 0402", Cap_Case=0402, Manufacturer=MuRata, Supplier Part Number 1=81-GRM1555C1H330JA1D, TempCo=C0G/NP0, Tolerance_%=5%, Value1=Unknown, Value2=50V, ValueDisplayed=33pF
C18 C20: library part CMP-0006687-2, "CAP, CERM, 330 pF, 50 V, +/- 10%, X7R, 0402", Cap_Case=0402, Manufacturer=MuRata, Supplier Part Number 1=490-3247-1-ND, TempCo=X7R, Tolerance_%=10%, Value1=Unknown, Value2=50V, ValueDisplayed=330pF
C22: library part CMP-0006267-3, "CAP, CERM, 0.47 uF, 10 V, +/- 10%, X5R, 0402", Cap_Case=0402, Manufacturer=TDK, Supplier Part Number 1=445-4989-1-ND, TempCo=X5R, Tolerance_%=10%, Value1=Unknown, Value2=10V, ValueDisplayed=0.47uF
C23: library part CMP-0006648-2, "CAP, CERM, 0.22 µF, 16 V, +/- 10%, X7R, 0402", Cap_Case=0402, Manufacturer=MuRata, Supplier Part Number 1=490-5418-1-ND, TempCo=X7R, Tolerance_%=10%, Value1=Unknown, Value2=16V, ValueDisplayed=0.22uF
C24: library part CMP-0009318-2, "CAP, CERM, 0.1 uF, 630 V, +/- 10%, X7R, 1808", Cap_Case=1808, Manufacturer=Kemet, Supplier Part Number 1=399-6515-1-ND, TempCo=X7R, Tolerance_%=10%, Value1=Unknown, Value2=630V, ValueDisplayed=0.1uF
C25 C100: library part CMP-0006352-2, "CAP, CERM, 0.01 uF, 25 V, +/- 10%, X7R, 0402", Cap_Case=0402, Manufacturer=MuRata, Supplier Part Number 1=490-6043-2-ND, TempCo=X7R, Tolerance_%=10%, Value1=Unknown, Value2=25V, ValueDisplayed=0.01uF
D1: library part CMP-0029150-2, "Diode, Switching, 200 V, 0.2 A, AEC-Q101, SOD-323", Manufacturer="ON Semiconductor", Value1=0.2A, Value2=1.25V
D2: library part CMP-0077025-2, "Diode, Schottky, 200 V, 3 A, PowerDI5", Manufacturer="Diodes Inc.", Value1=3A, Value2=0.78V
D3: library part CMP-0005821-3, "Diode, TVS, Bi, 16.2 V, SOD-323", Manufacturer=Toshiba, PartNumber=DF2B18FU,H3F, Value1=80W
D101: library part CMP-0077617-3, "Diode, Zener, 20 V, 500 mW, SOD-123", Manufacturer=Vishay-Semiconductor, Power_W=500mW, Value1=0.5W
J1: library part CMP-BK1, "Connector Socket Through Hole 17 position 0.050\" (1.27mm)", Current_A=1A, Digikey Part Number=GRPB171VWVN-RC-ND, Manufacturer="Sullins Connector Solutions", Operating Temperature Range="-40°C to +105°C", Part Number=GRPB171VWVN-RC
J2: library part CMP-0086278-1, "Header, 1.27mm, 4x2, Gold, R/A, TH", Current_A=1A, Manufacturer="Sullins Connector Solutions", Voltage_V=500V
J4: library part CMP-0054702-2, "Header, 50mil, 10x2, Gold, R/A, TH", Manufacturer="Sullins Connector Solutions", Supplier Part Number 1=S9017E-10-ND
J5 J7: library part CMP-0092135-1, Current_A=1A, Digikey Part Number=S9008E-04-ND, Manufacturer="Sullins Connector Solutions", Operating Temperature Range="-40°C to +125°C"
LOGO1: library part CMP-0074835-1, "IEC 61010-1 High Voltage Warning"
Q1 Q4: library part CMP-0000587-1, "MOSFET, N-CH, 30 V, 60 A, DQG0008A (VSON-CLIP-8)", Alternate Manufacturer=None, Manufacturer="Texas Instruments", Supplier Part Number 1=296-39994-1-ND, Value1=0.003, Value2="23 nC"
Q2: library part CMP-0067574-1, "MOSFET, N-CH, 600 V, 0.021 A, AEC-Q101, SOT-23", Alternate Manufacturer=None, Manufacturer="Infineon Technologies", PartNumber=BSS126H6327XTSA2, Supplier Part Number 1=BSS126H6327XTSA2CT-ND, Value1="? ohm", Value2="1.4 nC"
Q3: library part CMP-0078773-2, "Transistor, NPN, 40 V, 0.6 A, AEC-Q101, SOT-416", Manufacturer="ON Semiconductor", Value1="0.6 A"
Q200: library part CMP-0000039-3, "MOSFET, P-CH, -20 V, -0.43 A, AEC-Q101, SOT-523", Alternate Manufacturer=None, Manufacturer="Diodes Inc.", Value1=1
R1: library part CMP-0018610-3, "RES, 1.0 M, 5%, 0.25 W, AEC-Q200 Grade 0, 1206", Manufacturer=Vishay-Dale, Power_W=250mW, Supplier Part Number 1=541-1.0MECT-ND, TempCo="200 ppm/C", Tolerance_%=5%, Value2=0.25W, Value_Code=1M00, ValueDisplayed=1.0M
R2 R4 R30: library part CMP-0025984-3, "RES, 121 k, 1%, 0.063 W, AEC-Q200 Grade 0, 0402", Manufacturer=Vishay-Dale, Power_W=63mW, Supplier Part Number 1=541-121KLCT-ND, TempCo="100 ppm/C", Tolerance_%=1%, Value2=0.063W, Value_Code=121k
R3: library part CMP-0017256-2, "RES, 0.01, 1%, 0.5 W, 1206", Manufacturer="Stackpole Electronics Inc", Power_W=500mW, Supplier Part Number 1=CSR1206FK10L0CT-ND, TempCo="100 ppm/C", Tolerance_%=1%, Value2=0.5W, Value_Code=R010, ValueDisplayed=0.01
R5 R9: library part CMP-0026436-2, "RES, 511, 1%, 0.063 W, AEC-Q200 Grade 0, 0402", Manufacturer=Vishay-Dale, Power_W=63mW, Supplier Part Number 1=541-511LCT-ND, TempCo="100 ppm/C", Tolerance_%=1%, Value2=0.063W, Value_Code=511R, ValueDisplayed=511
R6 R29: library part CMP-0026437-2, "RES, 51.1 k, 1%, 0.063 W, AEC-Q200 Grade 0, 0402", Manufacturer=Vishay-Dale, Power_W=63mW, Supplier Part Number 1=541-51.1KLCT-ND, TempCo="100 ppm/C", Tolerance_%=1%, Value2=0.063W, Value_Code=51k1, ValueDisplayed=51.1k
R7 R32 R200: library part CMP-0025958-1, "RES, 10.0 k, 1%, 0.063 W, 0402", Manufacturer=Vishay-Dale, Power_W=63mW, Supplier Part Number 1=541-10.0KLCT-ND, TempCo="100 ppm/C", Tolerance_%=1%, Value2=0.063W, Value_Code=10k0, ValueDisplayed=10.0k
R8: library part CMP-0026620-3, "RES, 9.31 k, 1%, 0.063 W, AEC-Q200 Grade 0, 0402", Manufacturer=Vishay-Dale, Power_W=63mW, Supplier Part Number 1=541-9.31KLCT-ND, TempCo="100 ppm/C", Tolerance_%=1%, Value2=0.063W, Value_Code=9k31, ValueDisplayed=9.31k
R10: library part CMP-0026555-2, "RES, 7.50 k, 1%, 0.063 W, AEC-Q200 Grade 0, 0402", Manufacturer=Vishay-Dale, Power_W=63mW, Supplier Part Number 1=541-7.50KLCT-ND, TempCo="100 ppm/C", Tolerance_%=1%, Value2=0.063W, Value_Code=7k50, ValueDisplayed=7.50k
R11: library part CMP-0026793-1, "RES, 10.0 k, 0.1%, 0.063 W, 0402", Manufacturer=Rohm, Power_W=63mW, Supplier Part Number 1=RHM10.0KCDCT-ND, TempCo="100 ppm/C", Tolerance_%=0.1%, Value2=0.063W, Value_Code=10k0, ValueDisplayed=10.0k
R12 R22 R24 R25 R26: library part CMP-0026822-3, "RES, 0, 5%, 0.063 W, AEC-Q200 Grade 0, 0402", Manufacturer=Vishay-Dale, Power_W=63mW, Supplier Part Number 1=541-0.0JCT-ND, TempCo="200 ppm/C", Tolerance_%=5%, Value2=0.063W, Value_Code=0000, ValueDisplayed=0
R13: library part CMP-0026022-3, "RES, 150, 1%, 0.063 W, AEC-Q200 Grade 0, 0402", Manufacturer=Vishay-Dale, Power_W=63mW, Supplier Part Number 1=541-150LCT-ND, TempCo="100 ppm/C", Tolerance_%=1%, Value2=0.063W, Value_Code=150R, ValueDisplayed=150
R14: library part CMP-0026414-2, "RES, 4.99 k, 1%, 0.063 W, AEC-Q200 Grade 0, 0402", Manufacturer=Vishay-Dale, Power_W=63mW, Supplier Part Number 1=541-4.99KLCT-ND, TempCo="100 ppm/C", Tolerance_%=1%, Value2=0.063W, Value_Code=4k99, ValueDisplayed=4.99k
R15: library part CMP-0026158-2, "RES, 200 k, 1%, 0.063 W, AEC-Q200 Grade 0, 0402", Manufacturer=Vishay-Dale, Power_W=63mW, Supplier Part Number 1=541-200KLCT-ND, TempCo="100 ppm/C", Tolerance_%=1%, Value2=0.063W, Value_Code=200k
R16: library part CMP-0026776-1, "RES, 1.05 k, 0.1%, 0.063 W, 0402", Manufacturer=Panasonic, Power_W=63mW, Supplier Part Number 1=P33KDCCT-ND, TempCo="25 ppm/C", Tolerance_%=0.1%, Value2=0.063W, Value_Code=33k0, ValueDisplayed=1.05k
R17: library part CMP-0026162-2, "RES, 20.0 k, 1%, 0.063 W, AEC-Q200 Grade 0, 0402", Manufacturer=Vishay-Dale, Power_W=63mW, Supplier Part Number 1=541-20.0KLCT-ND, TempCo="100 ppm/C", Tolerance_%=1%, Value2=0.063W, Value_Code=20k0, ValueDisplayed=20.0k
R18: library part CMP-0026371-2, "RES, 41.2 k, 1%, 0.063 W, AEC-Q200 Grade 0, 0402", Manufacturer=Vishay-Dale, Power_W=63mW, Supplier Part Number 1=541-41.2KLCT-ND, TempCo="100 ppm/C", Tolerance_%=1%, Value2=0.063W, Value_Code=41k2, ValueDisplayed=41.2k
R19: library part CMP-0026815-1, "RES, 100 k, 0.1%, 0.063 W, 0402", Manufacturer="Susumu Co Ltd", Power_W=63mW, Supplier Part Number 1=RG10P100KBCT-ND, TempCo="25 ppm/C", Tolerance_%=0.1%, Value2=0.063W, Value_Code=100k
R20: library part CMP-0026776-1, "RES, 30.9 k, 0.1%, 0.063 W, 0402", Manufacturer=Panasonic, Power_W=63mW, Supplier Part Number 1=P33KDCCT-ND, TempCo="25 ppm/C", Tolerance_%=0.1%, Value2=0.063W, Value_Code=33k0, ValueDisplayed=30.9k
R21: library part CMP-0026056-3, "RES, 187 k, 1%, 0.063 W, AEC-Q200 Grade 0, 0402", Manufacturer=Vishay-Dale, Power_W=63mW, Supplier Part Number 1=541-187KLCT-ND, TempCo="100 ppm/C", Tolerance_%=1%, Value2=0.063W, Value_Code=187k
R23: library part CMP-0026535-2, "RES, 71.5 k, 1%, 0.063 W, AEC-Q200 Grade 0, 0402", Manufacturer=Vishay-Dale, Power_W=63mW, Supplier Part Number 1=541-71.5KLCT-ND, TempCo="100 ppm/C", Tolerance_%=1%, Value2=0.063W, Value_Code=71k5, ValueDisplayed=71.5k
R27: library part CMP-0025951-3, "RES, 100, 1%, 0.063 W, AEC-Q200 Grade 0, 0402", Manufacturer=Vishay-Dale, Power_W=63mW, Supplier Part Number 1=541-100LCT-ND, TempCo="100 ppm/C", Tolerance_%=1%, Value2=0.063W, Value_Code=100R, ValueDisplayed=100
R28: library part CMP-0025950-3, "RES, 100 k, 1%, 0.063 W, AEC-Q200 Grade 0, 0402", Manufacturer=Vishay-Dale, Power_W=63mW, Supplier Part Number 1=541-100KLCT-ND, TempCo="100 ppm/C", Tolerance_%=1%, Value2=0.063W, Value_Code=100k
R31: library part CMP-0026338-2, "RES, 3.74 k, 1%, 0.063 W, AEC-Q200 Grade 0, 0402", Manufacturer=Vishay-Dale, Power_W=63mW, Supplier Part Number 1=541-3.74KLCT-ND, TempCo="100 ppm/C", Tolerance_%=1%, Value2=0.063W, Value_Code=3k74, ValueDisplayed=3.74k
R201: library part CMP-0026088-3, "RES, 1.50 k, 1%, 0.063 W, AEC-Q200 Grade 0, 0402", Manufacturer=Vishay-Dale, Power_W=63mW, Supplier Part Number 1=541-1.50KLCT-ND, TempCo="100 ppm/C", Tolerance_%=1%, Value2=0.063W, Value_Code=1k50, ValueDisplayed=1.50k
RT1: library part CMP-0022434-4, "RES, 46.4 k, 1%, 0.1 W, AEC-Q200 Grade 0, 0603", Manufacturer=Vishay-Dale, Power_W=100mW, Supplier Part Number 1=541-46.4KHCT-ND, TempCo="100 ppm/C", Tolerance_%=1%, Value2=0.1W, Value_Code=46k4, ValueDisplayed=46.4k
U1: library part CMP-0093339-2, "Integrated 650-V GaN Half-Bridge for Active Clamp Flyback Converters", Manufacturer="Texas Instruments", Max Supply Voltage=26V, Min Supply Voltage=10V, Nominal Supply Current=20-1000uA, Operating Temperature Range="-40°C to +125°C", Output Voltage=650V, Part Number=LMG2610_epodB
U2: library part CMP-0089212-1, "Ideal Diode Controller with Load Dump Protection", Manufacturer="Texas Instruments", Max Supply Voltage=65V, Min Supply Voltage=3V, Nominal Supply Current=428uA, Operating Temperature Range="-40°C to +150°C"
U3: library part CMP-0086087-1, "UCC28782ARTW, RTW0024B (WQFN-24)", Alternate Manufacturer="Texas Instruments"
U4: library part CMP-0032800-2, "Precision Micropower Shunt Voltage Reference, 0.1% accuracy, 5 V, 15 ppm / degC, 15 mA, -40 to 85 degC, 5-pin SC70 (DCK), Green (RoHS & no Sb/Br)", Manufacturer="Texas Instruments", Rating=Catalog, Temp Coeff(Max)(ppm/ degree C)=100, Temp Coeff(Typ)(ppm/ degree C)=15
U5: library part CMP-0087394-2, "Optoisolator Transistor Output 5000Vrms 1 Channel 6-SO", Manufacturer=Toshiba
U6: library part CMP-0040524-2, "MicroPower, Rail-to-Rail Output, General Purpose Operational Amplifier, 2.7 to 36 V, -40 to 125 degC, 5-pin SOT23 (DRL5), Green (RoHS & no Sb/Br)", Manufacturer="Texas Instruments", Rating=Catalog, Total Supply Voltage(Max)(+5V is 5, +/-5V is 10)=36, Total Supply Voltage(Min)(+5V is 5, +/-5V is 10)=2.7
U7: library part CMP-0073863-3, "40-V, 450-mA, Low IQ, Low-Dropout Voltage Regulator with Power Good, DRB0008B (VSON-8)", Alternate Manufacturer="Texas Instruments", Alternate PartNumber=TPS7A1901DRBT

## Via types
v1: diameter 0.65, hole 0.32, Top Layer to Bottom Layer, 41 vias
v2: diameter 0.5, hole 0.2, Top Layer to Bottom Layer, 24 vias
v3: diameter 0.65, hole 0.32, Top Layer to Bottom Layer, tented bottom, 9 vias

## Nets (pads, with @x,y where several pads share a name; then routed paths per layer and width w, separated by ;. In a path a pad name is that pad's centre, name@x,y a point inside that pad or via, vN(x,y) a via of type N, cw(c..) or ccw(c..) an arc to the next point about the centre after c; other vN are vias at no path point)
5VREF: Q3.1 R7.1 R19.1 U4.3 | length 12.3
  Int2 (PWR) w0.3: v1(25.452,8.773) 25.905,8.32 25.905,2.552 v1(25.509,2.156)
  Bottom Layer w0.3: Q3.1@24.534,2.156 v1(25.509,2.156) U4.3@26.483,2.156 ; R19.1@25.251,7.986 25.251,8.572 v1(25.452,8.773) ; U4.3@26.583,2.156 27.725,2.156 27.958,2.389 27.958,2.472 28.428,2.941 R7.1@28.688,2.941
12VSB: C6.1 J2.3 J2.4 J2.6 Q4.1 Q4.2 Q4.3 U2.9 | length 19.8
  Top Layer w0.2: v1(28.232,11.112) 30.859,13.739 30.859,17.47 v1(32.046,18.657)
  Int1 (GND) w0.2: v1(28.232,11.112) 28.232,8.842 31.488,5.585 J2.4@31.488,2.866
  Bottom Layer w0.25: v1(32.046,18.657) 32.254,18.449 U2.9@32.254,17.629
CS: R9.1 R13.2 U1.32 | length 11.3
  Int1 (GND) w0.25: v3(8.646,18.449) 9.489,17.607 9.511,17.607 9.511,17.438 9.891,17.057 10.43,17.057 10.811,17.438 10.811,17.533 10.919,17.641 v1(14.986,17.641)
  Bottom Layer w0.2: U1.32@8.261,17.407 8.261,18.064 v3(8.646,18.449)
  Bottom Layer w0.25: v1(14.986,17.641) 14.986,16.975 15.386,16.575 R9.1@16.19,16.575 R13.2@16.19,15.816
DIS: J4.14 Q200.1 R200.1 | length 18.9
  Top Layer w0.2: J4.14@8.23,2.848 8.425,2.848 J4.14@8.437,2.86
  Int2 (PWR) w0.3: J4.14@8.437,2.86 10.161,4.583 10.161,16.752 9.812,17.101 9.593,17.32 9.486,17.427 9.486,17.986 9.719,18.22 v3(9.719,18.449)
  Bottom Layer w0.3: v3(9.719,18.449) 9.911,18.449 Q200.1@10.439,18.977 10.439,20.021 R200.1@10.431,20.029
FB: C18.1 R17.1 U3.6 | length 3
  Bottom Layer w0.25: U3.6@19.311,20.184 20.144,19.351 C18.1@20.144,18.555 R17.1@20.144,17.561
FLT: C21.1 Q200.3 RT1.1 U1.34 U3.1 | length 19.7
  Top Layer w0.4: v1(10.161,17.707) 10.681,18.228 10.681,20.15 10.743,20.15 15.037,24.444 17.474,24.444 v1(18.68,25.651)
  Bottom Layer w0.25: U1.34@9.011,16.642 9.353,16.642 10.161,17.449 v1(10.161,17.707) 10.49,17.377 Q200.3@10.939,17.377 ; v1(18.68,25.651) 18.684,25.654 RT1.1@19.675,25.654 19.557,25.536 C21.1@19.557,24.444 19.311,24.198 U3.1@19.311,22.684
